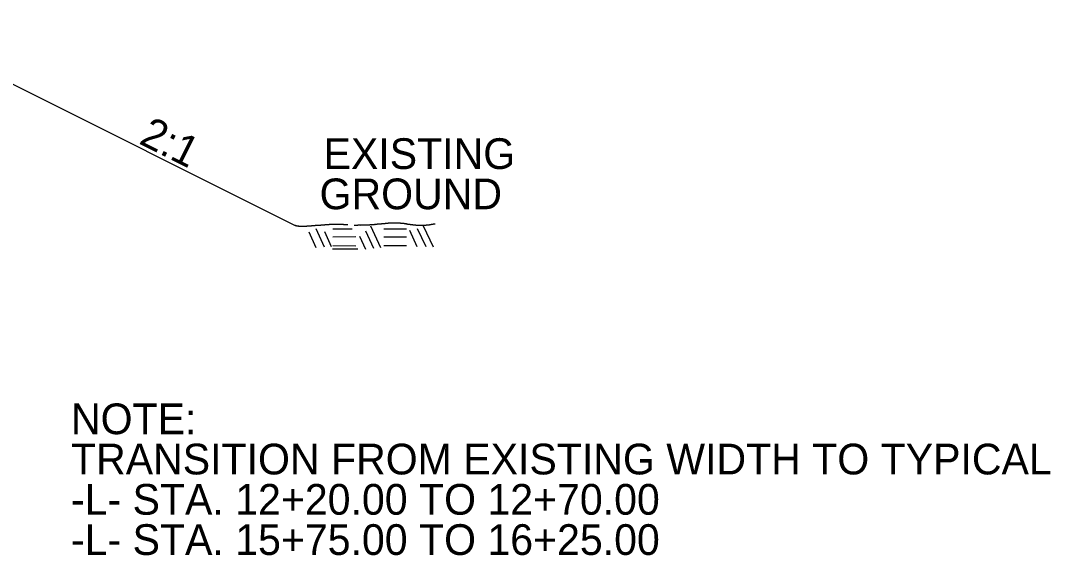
# Model space of a CAD drawing. Extents: x 1542177 to 1542464, y 45134 to 45344.
# Drawn here: x 1542284.79 to 1542304.92, y 45297.58 to 45308.03 of the extents above; entities that cross this region are included whole.
import ezdxf

# ---------------------------------------------------------------- set-up
doc = ezdxf.new("R2010")
doc.units = 0
doc.layers.add('Default', color=7, linetype='Continuous')

msp = doc.modelspace()

# ---------------------------------------------------------------- linework, layer by layer
at = {"layer": 'Default'}
for p, q in [((1542282.148, 45308.025), (1542290.155, 45304.022)), ((1542290.422, 45303.898), (1542290.563, 45303.594)), ((1542290.56, 45303.962), (1542290.725, 45303.607)), ((1542290.728, 45303.903), (1542290.862, 45303.614)), ((1542291.27, 45303.95), (1542290.893, 45303.95)), ((1542291.532, 45303.918), (1542291.689, 45303.58)), ((1542291.627, 45304.017), (1542291.824, 45303.595)), ((1542292.334, 45303.95), (1542291.887, 45303.95)), ((1542292.39, 45303.933), (1542292.538, 45303.614)), ((1542292.544, 45303.964), (1542292.708, 45303.615)), ((1542292.661, 45304.019), (1542292.852, 45303.606)), ((1542291.344, 45303.799), (1542290.893, 45303.798)), ((1542291.414, 45303.812), (1542291.529, 45303.561)), ((1542292.335, 45303.798), (1542291.887, 45303.798)), ((1542291.38, 45303.562), (1542290.885, 45303.562)), ((1542291.343, 45303.622), (1542290.895, 45303.623)), ((1542292.335, 45303.624), (1542291.887, 45303.624))]:
    msp.add_line(p, q, dxfattribs=at)
for points in [[(1542292.891, 45304.048), (1542292.891, 45304.049), (1542292.89, 45304.05), (1542292.889, 45304.051), (1542292.887, 45304.052), (1542292.884, 45304.051), (1542292.882, 45304.051), (1542292.88, 45304.051), (1542292.877, 45304.052), (1542292.874, 45304.051), (1542292.872, 45304.051), (1542292.87, 45304.049), (1542292.868, 45304.049), (1542292.866, 45304.048), (1542292.863, 45304.047), (1542292.861, 45304.047), (1542292.858, 45304.046), (1542292.856, 45304.046), (1542292.853, 45304.045), (1542292.851, 45304.045), (1542292.849, 45304.044), (1542292.847, 45304.043), (1542292.844, 45304.043), (1542292.841, 45304.044), (1542292.839, 45304.044), (1542292.836, 45304.043), (1542292.834, 45304.042), (1542292.831, 45304.042), (1542292.829, 45304.041), (1542292.827, 45304.043), (1542292.824, 45304.042), (1542292.822, 45304.041), (1542292.819, 45304.041), (1542292.816, 45304.04), (1542292.814, 45304.039), (1542292.812, 45304.038), (1542292.81, 45304.038), (1542292.807, 45304.037), (1542292.805, 45304.037), (1542292.802, 45304.037), (1542292.8, 45304.037), (1542292.797, 45304.037), (1542292.795, 45304.036), (1542292.793, 45304.036), (1542292.791, 45304.035), (1542292.788, 45304.035), (1542292.786, 45304.034), (1542292.783, 45304.033), (1542292.781, 45304.033), (1542292.778, 45304.032), (1542292.776, 45304.033), (1542292.774, 45304.033), (1542292.771, 45304.032), (1542292.769, 45304.031), (1542292.766, 45304.031), (1542292.764, 45304.03), (1542292.762, 45304.03), (1542292.76, 45304.029), (1542292.756, 45304.029), (1542292.753, 45304.03), (1542292.75, 45304.029), (1542292.747, 45304.029), (1542292.745, 45304.027), (1542292.743, 45304.027), (1542292.739, 45304.027), (1542292.735, 45304.027), (1542292.732, 45304.027), (1542292.729, 45304.027), (1542292.727, 45304.028), (1542292.725, 45304.028), (1542292.721, 45304.027), (1542292.718, 45304.027), (1542292.714, 45304.026), (1542292.712, 45304.026), (1542292.71, 45304.025), (1542292.707, 45304.025), (1542292.704, 45304.025), (1542292.701, 45304.026), (1542292.697, 45304.026), (1542292.694, 45304.026), (1542292.692, 45304.026), (1542292.689, 45304.026), (1542292.685, 45304.026), (1542292.682, 45304.025), (1542292.678, 45304.025), (1542292.674, 45304.025), (1542292.671, 45304.025), (1542292.668, 45304.025), (1542292.665, 45304.025), (1542292.662, 45304.026), (1542292.66, 45304.026), (1542292.658, 45304.026), (1542292.655, 45304.025), (1542292.653, 45304.025), (1542292.65, 45304.025), (1542292.646, 45304.026), (1542292.643, 45304.026), (1542292.639, 45304.026), (1542292.635, 45304.026), (1542292.631, 45304.026), (1542292.629, 45304.026), (1542292.627, 45304.025), (1542292.625, 45304.025), (1542292.621, 45304.025), (1542292.618, 45304.026), (1542292.614, 45304.026), (1542292.611, 45304.026), (1542292.608, 45304.026), (1542292.606, 45304.026), (1542292.603, 45304.026), (1542292.601, 45304.025), (1542292.599, 45304.025), (1542292.597, 45304.025), (1542292.595, 45304.025), (1542292.593, 45304.025), (1542292.59, 45304.025), (1542292.588, 45304.025), (1542292.586, 45304.025), (1542292.584, 45304.025), (1542292.581, 45304.025), (1542292.579, 45304.025), (1542292.576, 45304.025), (1542292.574, 45304.025), (1542292.571, 45304.025), (1542292.569, 45304.025), (1542292.566, 45304.025), (1542292.563, 45304.025), (1542292.561, 45304.025), (1542292.559, 45304.025), (1542292.557, 45304.025), (1542292.555, 45304.025), (1542292.553, 45304.025), (1542292.551, 45304.025), (1542292.547, 45304.025), (1542292.543, 45304.025), (1542292.539, 45304.025), (1542292.536, 45304.025), (1542292.534, 45304.025), (1542292.531, 45304.025), (1542292.53, 45304.025), (1542292.528, 45304.025), (1542292.526, 45304.025), (1542292.522, 45304.025), (1542292.518, 45304.027), (1542292.514, 45304.027), (1542292.512, 45304.027), (1542292.509, 45304.028), (1542292.507, 45304.028), (1542292.504, 45304.028), (1542292.5, 45304.027), (1542292.497, 45304.027), (1542292.493, 45304.027), (1542292.489, 45304.029), (1542292.485, 45304.03), (1542292.481, 45304.03), (1542292.478, 45304.029), (1542292.475, 45304.029), (1542292.471, 45304.029), (1542292.467, 45304.03), (1542292.464, 45304.031), (1542292.46, 45304.031), (1542292.457, 45304.032), (1542292.454, 45304.033), (1542292.45, 45304.033), (1542292.446, 45304.033), (1542292.443, 45304.033), (1542292.44, 45304.033), (1542292.438, 45304.034), (1542292.436, 45304.034), (1542292.433, 45304.035), (1542292.431, 45304.036), (1542292.429, 45304.036), (1542292.425, 45304.037), (1542292.421, 45304.036), (1542292.417, 45304.036), (1542292.414, 45304.037), (1542292.412, 45304.037), (1542292.41, 45304.038), (1542292.407, 45304.038), (1542292.405, 45304.039), (1542292.403, 45304.039), (1542292.4, 45304.04), (1542292.398, 45304.04), (1542292.396, 45304.04), (1542292.391, 45304.04), (1542292.385, 45304.04), (1542292.379, 45304.041), (1542292.377, 45304.042), (1542292.374, 45304.043), (1542292.371, 45304.043), (1542292.369, 45304.044), (1542292.366, 45304.045), (1542292.364, 45304.045), (1542292.362, 45304.046), (1542292.359, 45304.045), (1542292.357, 45304.045), (1542292.353, 45304.045), (1542292.35, 45304.048), (1542292.346, 45304.048), (1542292.344, 45304.049), (1542292.341, 45304.048), (1542292.338, 45304.049), (1542292.335, 45304.049), (1542292.332, 45304.052), (1542292.329, 45304.053), (1542292.326, 45304.053), (1542292.324, 45304.052), (1542292.321, 45304.052), (1542292.319, 45304.053), (1542292.317, 45304.053), (1542292.315, 45304.054), (1542292.312, 45304.055), (1542292.31, 45304.056), (1542292.307, 45304.056), (1542292.305, 45304.057), (1542292.302, 45304.057), (1542292.299, 45304.058), (1542292.296, 45304.058), (1542292.292, 45304.059), (1542292.289, 45304.059), (1542292.286, 45304.059), (1542292.284, 45304.059), (1542292.282, 45304.059), (1542292.28, 45304.059), (1542292.278, 45304.061), (1542292.276, 45304.061), (1542292.273, 45304.061), (1542292.27, 45304.061), (1542292.267, 45304.061), (1542292.265, 45304.061), (1542292.263, 45304.061), (1542292.26, 45304.061), (1542292.257, 45304.061), (1542292.253, 45304.062), (1542292.25, 45304.063), (1542292.247, 45304.063), (1542292.244, 45304.063), (1542292.242, 45304.063), (1542292.24, 45304.063), (1542292.238, 45304.065), (1542292.236, 45304.065), (1542292.232, 45304.065), (1542292.228, 45304.064), (1542292.224, 45304.064), (1542292.222, 45304.064), (1542292.22, 45304.065), (1542292.217, 45304.065), (1542292.215, 45304.065), (1542292.213, 45304.066), (1542292.211, 45304.066), (1542292.208, 45304.066), (1542292.206, 45304.066), (1542292.203, 45304.066), (1542292.201, 45304.066), (1542292.199, 45304.066), (1542292.197, 45304.066), (1542292.194, 45304.066), (1542292.192, 45304.066), (1542292.19, 45304.066), (1542292.188, 45304.066), (1542292.185, 45304.066), (1542292.183, 45304.066), (1542292.18, 45304.066), (1542292.178, 45304.068), (1542292.175, 45304.068), (1542292.173, 45304.068), (1542292.17, 45304.068), (1542292.168, 45304.068), (1542292.166, 45304.068), (1542292.163, 45304.068), (1542292.16, 45304.068), (1542292.158, 45304.068), (1542292.157, 45304.068), (1542292.155, 45304.068), (1542292.15, 45304.068), (1542292.146, 45304.068), (1542292.142, 45304.068), (1542292.138, 45304.068), (1542292.133, 45304.068), (1542292.129, 45304.068), (1542292.127, 45304.068), (1542292.124, 45304.068), (1542292.121, 45304.068), (1542292.114, 45304.067), (1542292.107, 45304.069), (1542292.1, 45304.068), (1542292.098, 45304.068), (1542292.096, 45304.068), (1542292.094, 45304.068), (1542292.091, 45304.068), (1542292.089, 45304.068), (1542292.086, 45304.068), (1542292.084, 45304.068), (1542292.082, 45304.068), (1542292.079, 45304.068), (1542292.077, 45304.068), (1542292.074, 45304.068), (1542292.072, 45304.068), (1542292.068, 45304.068), (1542292.064, 45304.068), (1542292.061, 45304.068), (1542292.058, 45304.068), (1542292.055, 45304.068), (1542292.053, 45304.068), (1542292.051, 45304.068), (1542292.048, 45304.068), (1542292.046, 45304.068), (1542292.044, 45304.068), (1542292.041, 45304.068), (1542292.039, 45304.068), (1542292.037, 45304.068), (1542292.034, 45304.068), (1542292.032, 45304.068), (1542292.03, 45304.068), (1542292.027, 45304.067), (1542292.025, 45304.067), (1542292.023, 45304.067), (1542292.02, 45304.068), (1542292.018, 45304.068), (1542292.016, 45304.068), (1542292.014, 45304.068), (1542292.012, 45304.068), (1542292.008, 45304.068), (1542292.005, 45304.067), (1542292.001, 45304.067), (1542291.998, 45304.067), (1542291.996, 45304.067), (1542291.993, 45304.067), (1542291.991, 45304.067), (1542291.988, 45304.066), (1542291.986, 45304.066), (1542291.984, 45304.066), (1542291.982, 45304.067), (1542291.979, 45304.067), (1542291.977, 45304.067), (1542291.975, 45304.064), (1542291.972, 45304.064), (1542291.97, 45304.064), (1542291.967, 45304.065), (1542291.965, 45304.065), (1542291.962, 45304.065), (1542291.96, 45304.065), (1542291.957, 45304.065), (1542291.954, 45304.065), (1542291.95, 45304.064), (1542291.946, 45304.064), (1542291.944, 45304.064), (1542291.941, 45304.063), (1542291.939, 45304.062), (1542291.937, 45304.062), (1542291.935, 45304.063), (1542291.933, 45304.062), (1542291.93, 45304.062), (1542291.928, 45304.061), (1542291.925, 45304.061), (1542291.91, 45304.058), (1542291.895, 45304.057), (1542291.879, 45304.055), (1542291.877, 45304.055), (1542291.875, 45304.056), (1542291.872, 45304.055), (1542291.87, 45304.055), (1542291.867, 45304.054), (1542291.864, 45304.053), (1542291.862, 45304.053), (1542291.861, 45304.053), (1542291.859, 45304.053), (1542291.856, 45304.053), (1542291.853, 45304.054), (1542291.851, 45304.054), (1542291.848, 45304.054), (1542291.846, 45304.052), (1542291.844, 45304.052), (1542291.841, 45304.052), (1542291.839, 45304.052), (1542291.837, 45304.052), (1542291.831, 45304.052), (1542291.825, 45304.052), (1542291.819, 45304.052), (1542291.816, 45304.052), (1542291.814, 45304.051), (1542291.811, 45304.05), (1542291.809, 45304.05), (1542291.806, 45304.05), (1542291.804, 45304.05), (1542291.801, 45304.05), (1542291.799, 45304.048), (1542291.796, 45304.048), (1542291.788, 45304.047), (1542291.78, 45304.047), (1542291.772, 45304.047), (1542291.765, 45304.046), (1542291.759, 45304.046), (1542291.752, 45304.045), (1542291.748, 45304.045), (1542291.744, 45304.044), (1542291.74, 45304.043), (1542291.737, 45304.043), (1542291.733, 45304.042), (1542291.729, 45304.041), (1542291.727, 45304.041), (1542291.724, 45304.042), (1542291.722, 45304.041), (1542291.719, 45304.041), (1542291.717, 45304.039), (1542291.715, 45304.039), (1542291.713, 45304.039), (1542291.71, 45304.04), (1542291.708, 45304.039), (1542291.706, 45304.039), (1542291.703, 45304.038), (1542291.701, 45304.038), (1542291.697, 45304.038), (1542291.694, 45304.038), (1542291.69, 45304.037), (1542291.688, 45304.037), (1542291.685, 45304.037), (1542291.682, 45304.036), (1542291.68, 45304.036), (1542291.677, 45304.036), (1542291.674, 45304.036), (1542291.669, 45304.035), (1542291.663, 45304.036), (1542291.657, 45304.036), (1542291.654, 45304.036), (1542291.65, 45304.034), (1542291.646, 45304.034), (1542291.644, 45304.034), (1542291.642, 45304.034), (1542291.639, 45304.034), (1542291.634, 45304.034), (1542291.628, 45304.034), (1542291.623, 45304.034), (1542291.62, 45304.034), (1542291.618, 45304.034), (1542291.616, 45304.034), (1542291.613, 45304.033), (1542291.611, 45304.032), (1542291.609, 45304.032), (1542291.606, 45304.032), (1542291.604, 45304.032), (1542291.601, 45304.032), (1542291.595, 45304.032), (1542291.589, 45304.032), (1542291.583, 45304.032), (1542291.581, 45304.032), (1542291.578, 45304.032), (1542291.576, 45304.032), (1542291.573, 45304.032), (1542291.571, 45304.03), (1542291.568, 45304.03), (1542291.566, 45304.03), (1542291.563, 45304.03), (1542291.561, 45304.03), (1542291.555, 45304.03), (1542291.549, 45304.03), (1542291.543, 45304.03), (1542291.541, 45304.03), (1542291.539, 45304.03), (1542291.536, 45304.03), (1542291.534, 45304.03), (1542291.531, 45304.03), (1542291.528, 45304.03), (1542291.523, 45304.03), (1542291.517, 45304.029), (1542291.512, 45304.029), (1542291.51, 45304.029), (1542291.508, 45304.029), (1542291.506, 45304.029), (1542291.501, 45304.028), (1542291.496, 45304.028), (1542291.491, 45304.028), (1542291.488, 45304.028), (1542291.485, 45304.029), (1542291.483, 45304.029), (1542291.477, 45304.029), (1542291.471, 45304.029), (1542291.465, 45304.029), (1542291.456, 45304.029), (1542291.448, 45304.028), (1542291.439, 45304.028), (1542291.433, 45304.028), (1542291.427, 45304.026), (1542291.421, 45304.026), (1542291.419, 45304.026), (1542291.418, 45304.027), (1542291.416, 45304.027), (1542291.413, 45304.027), (1542291.411, 45304.027), (1542291.408, 45304.027), (1542291.402, 45304.027), (1542291.396, 45304.027), (1542291.39, 45304.027), (1542291.387, 45304.027), (1542291.385, 45304.027), (1542291.383, 45304.027), (1542291.381, 45304.027), (1542291.379, 45304.025), (1542291.376, 45304.025), (1542291.374, 45304.024), (1542291.371, 45304.024), (1542291.368, 45304.024), (1542291.366, 45304.024), (1542291.364, 45304.024), (1542291.362, 45304.024), (1542291.36, 45304.025), (1542291.357, 45304.025), (1542291.355, 45304.024), (1542291.352, 45304.024), (1542291.35, 45304.023), (1542291.348, 45304.023), (1542291.345, 45304.023), (1542291.342, 45304.023), (1542291.339, 45304.023), (1542291.337, 45304.023), (1542291.335, 45304.024), (1542291.332, 45304.024), (1542291.33, 45304.024), (1542291.328, 45304.023), (1542291.326, 45304.023), (1542291.323, 45304.023), (1542291.32, 45304.023), (1542291.318, 45304.023), (1542291.316, 45304.023), (1542291.314, 45304.021), (1542291.311, 45304.021), (1542291.311, 45304.021), (1542291.311, 45304.021), (1542291.311, 45304.021)], [(1542291.187, 45304.036), (1542291.184, 45304.036), (1542291.182, 45304.037), (1542291.179, 45304.037), (1542291.173, 45304.038), (1542291.168, 45304.037), (1542291.162, 45304.037), (1542291.16, 45304.038), (1542291.158, 45304.039), (1542291.155, 45304.039), (1542291.149, 45304.039), (1542291.143, 45304.039), (1542291.137, 45304.039), (1542291.129, 45304.039), (1542291.12, 45304.039), (1542291.112, 45304.039), (1542291.106, 45304.039), (1542291.1, 45304.041), (1542291.094, 45304.041), (1542291.088, 45304.041), (1542291.082, 45304.04), (1542291.076, 45304.04), (1542291.074, 45304.041), (1542291.072, 45304.041), (1542291.069, 45304.041), (1542291.064, 45304.041), (1542291.058, 45304.041), (1542291.052, 45304.041), (1542291.05, 45304.041), (1542291.047, 45304.041), (1542291.045, 45304.041), (1542291.039, 45304.041), (1542291.032, 45304.041), (1542291.026, 45304.04), (1542291.024, 45304.04), (1542291.021, 45304.04), (1542291.019, 45304.04), (1542291.016, 45304.04), (1542291.014, 45304.04), (1542291.011, 45304.04), (1542291.006, 45304.04), (1542291, 45304.04), (1542290.995, 45304.04), (1542290.989, 45304.04), (1542290.983, 45304.04), (1542290.977, 45304.04), (1542290.973, 45304.041), (1542290.97, 45304.041), (1542290.966, 45304.041), (1542290.961, 45304.041), (1542290.956, 45304.04), (1542290.951, 45304.04), (1542290.949, 45304.04), (1542290.946, 45304.041), (1542290.944, 45304.041), (1542290.942, 45304.041), (1542290.94, 45304.041), (1542290.937, 45304.04), (1542290.935, 45304.04), (1542290.932, 45304.04), (1542290.929, 45304.04), (1542290.927, 45304.04), (1542290.925, 45304.041), (1542290.923, 45304.041), (1542290.919, 45304.041), (1542290.915, 45304.041), (1542290.911, 45304.041), (1542290.909, 45304.041), (1542290.907, 45304.041), (1542290.905, 45304.041), (1542290.902, 45304.041), (1542290.9, 45304.041), (1542290.897, 45304.041), (1542290.895, 45304.041), (1542290.893, 45304.04), (1542290.891, 45304.04), (1542290.889, 45304.04), (1542290.886, 45304.04), (1542290.884, 45304.04), (1542290.882, 45304.04), (1542290.881, 45304.04), (1542290.879, 45304.04), (1542290.876, 45304.04), (1542290.873, 45304.04), (1542290.871, 45304.04), (1542290.868, 45304.04), (1542290.866, 45304.04), (1542290.863, 45304.04), (1542290.86, 45304.04), (1542290.857, 45304.041), (1542290.854, 45304.041), (1542290.851, 45304.041), (1542290.848, 45304.041), (1542290.844, 45304.041), (1542290.839, 45304.041), (1542290.834, 45304.04), (1542290.829, 45304.04), (1542290.827, 45304.04), (1542290.825, 45304.04), (1542290.823, 45304.04), (1542290.82, 45304.04), (1542290.818, 45304.038), (1542290.816, 45304.038), (1542290.813, 45304.038), (1542290.811, 45304.039), (1542290.809, 45304.039), (1542290.801, 45304.038), (1542290.792, 45304.037), (1542290.784, 45304.037), (1542290.778, 45304.037), (1542290.772, 45304.037), (1542290.766, 45304.037), (1542290.764, 45304.037), (1542290.762, 45304.037), (1542290.759, 45304.037), (1542290.757, 45304.037), (1542290.754, 45304.036), (1542290.752, 45304.036), (1542290.749, 45304.035), (1542290.747, 45304.034), (1542290.744, 45304.033), (1542290.742, 45304.033), (1542290.74, 45304.033), (1542290.738, 45304.033), (1542290.735, 45304.033), (1542290.733, 45304.032), (1542290.73, 45304.031), (1542290.724, 45304.031), (1542290.718, 45304.032), (1542290.712, 45304.031), (1542290.709, 45304.031), (1542290.705, 45304.029), (1542290.702, 45304.029), (1542290.699, 45304.029), (1542290.696, 45304.029), (1542290.693, 45304.029), (1542290.69, 45304.029), (1542290.687, 45304.03), (1542290.683, 45304.03), (1542290.681, 45304.03), (1542290.679, 45304.029), (1542290.677, 45304.028), (1542290.672, 45304.028), (1542290.667, 45304.028), (1542290.662, 45304.027), (1542290.66, 45304.027), (1542290.657, 45304.026), (1542290.655, 45304.026), (1542290.653, 45304.026), (1542290.65, 45304.026), (1542290.648, 45304.026), (1542290.646, 45304.026), (1542290.644, 45304.026), (1542290.642, 45304.026), (1542290.636, 45304.026), (1542290.63, 45304.026), (1542290.624, 45304.026), (1542290.622, 45304.026), (1542290.619, 45304.025), (1542290.616, 45304.025), (1542290.614, 45304.025), (1542290.611, 45304.024), (1542290.609, 45304.024), (1542290.606, 45304.024), (1542290.603, 45304.024), (1542290.601, 45304.024), (1542290.599, 45304.024), (1542290.597, 45304.022), (1542290.594, 45304.022), (1542290.592, 45304.022), (1542290.59, 45304.022), (1542290.588, 45304.022), (1542290.585, 45304.023), (1542290.583, 45304.023), (1542290.58, 45304.023), (1542290.578, 45304.023), (1542290.575, 45304.023), (1542290.573, 45304.022), (1542290.57, 45304.022), (1542290.568, 45304.021), (1542290.566, 45304.021), (1542290.564, 45304.021), (1542290.562, 45304.021), (1542290.56, 45304.021), (1542290.557, 45304.021), (1542290.554, 45304.021), (1542290.552, 45304.021), (1542290.549, 45304.021), (1542290.547, 45304.019), (1542290.545, 45304.019), (1542290.541, 45304.019), (1542290.538, 45304.019), (1542290.534, 45304.019), (1542290.532, 45304.018), (1542290.529, 45304.018), (1542290.527, 45304.017), (1542290.524, 45304.017), (1542290.52, 45304.018), (1542290.516, 45304.018), (1542290.514, 45304.017), (1542290.512, 45304.016), (1542290.51, 45304.016), (1542290.506, 45304.015), (1542290.503, 45304.014), (1542290.499, 45304.014), (1542290.495, 45304.013), (1542290.492, 45304.014), (1542290.488, 45304.014), (1542290.486, 45304.014), (1542290.483, 45304.014), (1542290.48, 45304.014), (1542290.472, 45304.013), (1542290.464, 45304.012), (1542290.456, 45304.012), (1542290.452, 45304.011), (1542290.449, 45304.012), (1542290.445, 45304.011), (1542290.443, 45304.011), (1542290.44, 45304.01), (1542290.437, 45304.01), (1542290.435, 45304.01), (1542290.433, 45304.01), (1542290.431, 45304.01), (1542290.428, 45304.01), (1542290.426, 45304.01), (1542290.423, 45304.01), (1542290.419, 45304.01), (1542290.416, 45304.009), (1542290.412, 45304.009), (1542290.41, 45304.009), (1542290.408, 45304.009), (1542290.406, 45304.009), (1542290.403, 45304.008), (1542290.401, 45304.008), (1542290.398, 45304.008), (1542290.395, 45304.008), (1542290.391, 45304.007), (1542290.388, 45304.007), (1542290.386, 45304.006), (1542290.383, 45304.006), (1542290.381, 45304.006), (1542290.378, 45304.006), (1542290.375, 45304.007), (1542290.373, 45304.007), (1542290.369, 45304.007), (1542290.366, 45304.004), (1542290.363, 45304.004), (1542290.36, 45304.004), (1542290.358, 45304.004), (1542290.355, 45304.004), (1542290.353, 45304.005), (1542290.35, 45304.005), (1542290.348, 45304.005), (1542290.338, 45304.005), (1542290.329, 45304.003), (1542290.32, 45304.003), (1542290.314, 45304.003), (1542290.308, 45304.003), (1542290.302, 45304.003), (1542290.3, 45304.003), (1542290.297, 45304.003), (1542290.295, 45304.003), (1542290.293, 45304.003), (1542290.29, 45304.003), (1542290.288, 45304.003), (1542290.282, 45304.003), (1542290.276, 45304.002), (1542290.27, 45304.002), (1542290.268, 45304.002), (1542290.266, 45304.004), (1542290.264, 45304.004), (1542290.257, 45304.004), (1542290.251, 45304.004), (1542290.244, 45304.004), (1542290.242, 45304.004), (1542290.24, 45304.004), (1542290.238, 45304.004), (1542290.235, 45304.004), (1542290.233, 45304.007), (1542290.231, 45304.007), (1542290.225, 45304.008), (1542290.219, 45304.006), (1542290.213, 45304.007), (1542290.211, 45304.007), (1542290.209, 45304.008), (1542290.207, 45304.008), (1542290.204, 45304.009), (1542290.202, 45304.009), (1542290.199, 45304.01), (1542290.197, 45304.011), (1542290.194, 45304.011), (1542290.192, 45304.012), (1542290.188, 45304.013), (1542290.184, 45304.015), (1542290.18, 45304.016), (1542290.178, 45304.016), (1542290.175, 45304.015), (1542290.172, 45304.016), (1542290.17, 45304.016), (1542290.168, 45304.017), (1542290.166, 45304.018), (1542290.163, 45304.019), (1542290.161, 45304.02), (1542290.159, 45304.021), (1542290.158, 45304.021), (1542290.156, 45304.022), (1542290.155, 45304.022)]]:
    msp.add_open_spline(points, degree=3, dxfattribs=at)

# ---------------------------------------------------------------- texts
msp.add_text('2:1', height=0.6, rotation=333.4349, dxfattribs=at).set_placement((1542287.083, 45305.632))
for s, p in [('EXISTING', (1542290.712, 45305.127)), ('GROUND', (1542290.634, 45304.341)), ('NOTE:', (1542285.776, 45299.947)), ('TRANSITION FROM EXISTING WIDTH TO TYPICAL', (1542285.776, 45299.161)), ('-L- STA. 12+20.00 TO 12+70.00', (1542285.776, 45298.374)), ('-L- STA. 15+75.00 TO 16+25.00', (1542285.776, 45297.588))]:
    msp.add_text(s, height=0.6, dxfattribs=at).set_placement(p)

doc.saveas('drawing.dxf')
